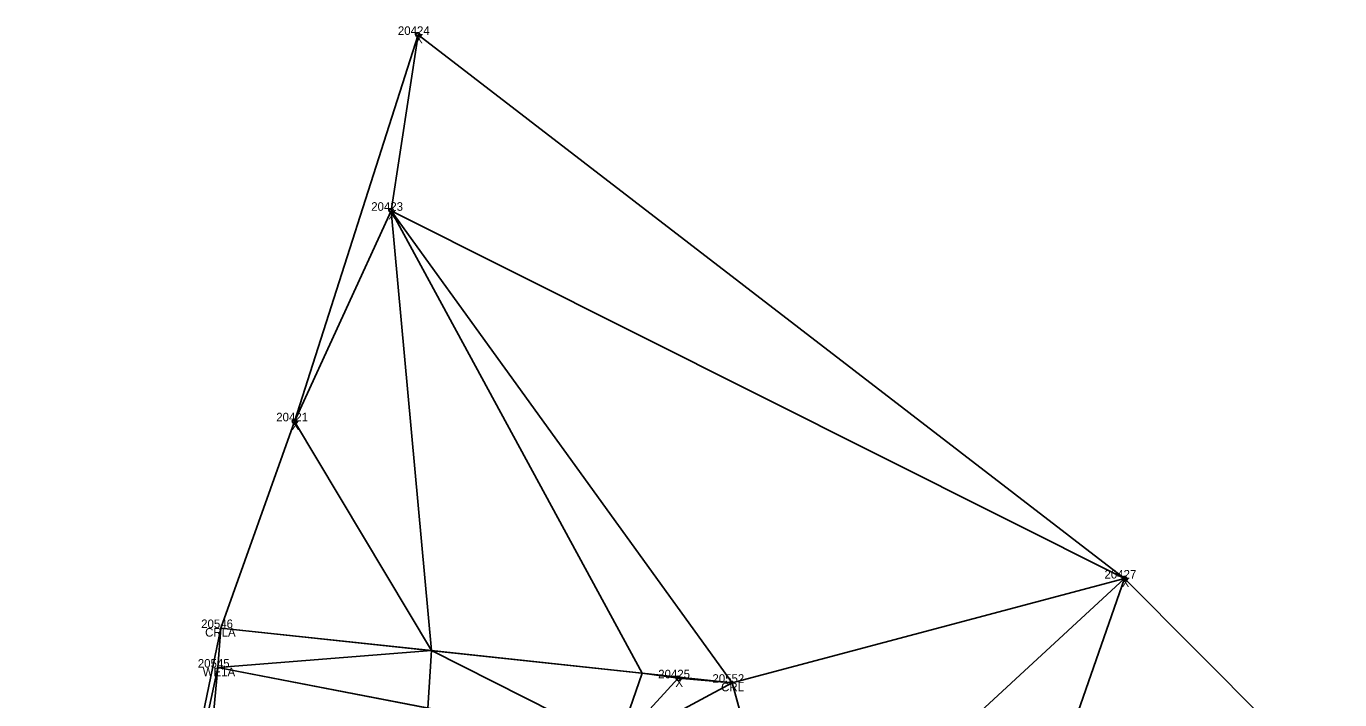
# Model space of a CAD drawing. Extents: x 1966740 to 1969291, y 1117379 to 1118460.
# Drawn here: x 1967829.6 to 1967983.3, y 1118381.7 to 1118460.4 of the extents above; entities that cross this region are included whole.
import ezdxf

# ---------------------------------------------------------------- set-up
doc = ezdxf.new("R2010")
doc.units = 0
for name, color, linetype in [('Level 10', 7, 'Continuous'), ('Level 30', 7, 'Continuous'), ('Level 35', 7, 'Continuous'), ('Level 50', 7, 'Continuous'), ('Level 52', 7, 'Continuous'), ('Level 60', 7, 'Continuous'), ('Level 61', 7, 'Continuous'), ('Level 62', 7, 'Continuous')]:
    doc.layers.add(name, color=color, linetype=linetype)

msp = doc.modelspace()

# ---------------------------------------------------------------- linework, layer by layer
at = {"layer": 'Level 10'}
for points in [[(1967852.4, 1118390.04), (1967912.21, 1118383.64), (1967925.08, 1118336.82), (1967944.14, 1118294.4), (1967946.67, 1118243.15), (1967961.58, 1118191.28), (1967922.84, 1118148.62), (1967880.18, 1118117.11), (1967858.72, 1118073.64), (1967843.96, 1118030.69), (1967829.77, 1117984.65), (1967829.63, 1117934.73), (1967834.65, 1117903.36)], [(1967852.05, 1118385.41), (1967898.77, 1118376.41), (1967924.08, 1118337.23), (1967939.81, 1118294.93), (1967943.5, 1118242.16), (1967952.29, 1118191.75), (1967920.83, 1118149.81), (1967879.07, 1118118.61), (1967857.7, 1118074.04)]]:
    msp.add_lwpolyline(points, dxfattribs=at)
at = {"layer": 'Level 30'}
for centre in [(1967875.46, 1118459.42), (1967872.32, 1118438.85), (1967860.99, 1118414.22), (1967958.1, 1118395.83), (1967905.89, 1118384.16)]:
    msp.add_circle(centre, 0.25, dxfattribs=at)
at = {"layer": 'Level 35'}
for points in [[(1967860.99, 1118414.22), (1967875.46, 1118459.42), (1967872.32, 1118438.85)], [(1967872.32, 1118438.85), (1967875.46, 1118459.42), (1967958.1, 1118395.83)], [(1967860.99, 1118414.22), (1967872.32, 1118438.85), (1967877.03, 1118387.41)], [(1967872.32, 1118438.85), (1967958.1, 1118395.83), (1967912.21, 1118383.64)], [(1967872.32, 1118438.85), (1967912.21, 1118383.64), (1967901.66, 1118384.77)], [(1967872.32, 1118438.85), (1967901.66, 1118384.77), (1967877.03, 1118387.41)], [(1967852.4, 1118390.04), (1967860.99, 1118414.22), (1967877.03, 1118387.41)], [(1967912.21, 1118383.64), (1967958.1, 1118395.83), (1967918.83, 1118359.56)], [(1967918.83, 1118359.56), (1967958.1, 1118395.83), (1967939.99, 1118343.92)], [(1967939.99, 1118343.92), (1967958.1, 1118395.83), (1967983.26, 1118370.54)], [(1967836.22, 1118311.82), (1967852.4, 1118390.04), (1967852.05, 1118385.41)], [(1967852.05, 1118385.41), (1967852.4, 1118390.04), (1967877.03, 1118387.41)], [(1967852.05, 1118385.41), (1967877.03, 1118387.41), (1967876.59, 1118380.68)], [(1967876.59, 1118380.68), (1967877.03, 1118387.41), (1967898.77, 1118376.41)], [(1967877.03, 1118387.41), (1967901.66, 1118384.77), (1967898.77, 1118376.41)], [(1967836.22, 1118311.82), (1967852.05, 1118385.41), (1967848.72, 1118350.07)], [(1967848.72, 1118350.07), (1967852.05, 1118385.41), (1967876.59, 1118380.68)], [(1967898.77, 1118376.41), (1967901.66, 1118384.77), (1967905.89, 1118384.16)], [(1967901.66, 1118384.77), (1967912.21, 1118383.64), (1967905.89, 1118384.16)], [(1967898.77, 1118376.41), (1967905.89, 1118384.16), (1967912.21, 1118383.64)], [(1967898.77, 1118376.41), (1967912.21, 1118383.64), (1967918.83, 1118359.56)]]:
    msp.add_lwpolyline(points, close=True, dxfattribs=at)
at = {"layer": 'Level 50'}
for centre in [(1967852.4, 1118390.04), (1967852.05, 1118385.41), (1967912.21, 1118383.64)]:
    msp.add_circle(centre, 0.001, dxfattribs=at)

# ---------------------------------------------------------------- texts
at = {"layer": 'Level 52'}
for s, p in [('20424', (1967873.1, 1118459.42)), ('20423', (1967869.98, 1118438.85)), ('20421', (1967858.87, 1118414.22)), ('20427', (1967955.75, 1118395.83)), ('20425', (1967903.55, 1118384.16))]:
    msp.add_text(s, height=1, dxfattribs=at).set_placement(p)
at = {"layer": 'Level 60'}
for s, p in [('CRLA', (1967850.55, 1118389.04)), ('WE1A', (1967850.27, 1118384.41)), ('CRL', (1967910.91, 1118382.64))]:
    msp.add_text(s, height=1, dxfattribs=at).set_placement(p)
at = {"layer": 'Level 61'}
for s, p in [('20546', (1967850.09, 1118390.04)), ('20545', (1967849.7, 1118385.41)), ('20552', (1967909.89, 1118383.64))]:
    msp.add_text(s, height=1, dxfattribs=at).set_placement(p)
at = {"layer": 'Level 62'}
for p in [(1967875.13, 1118458.42), (1967871.99, 1118437.85), (1967860.66, 1118413.22), (1967957.76, 1118394.83), (1967905.56, 1118383.16)]:
    msp.add_text('X', height=1, dxfattribs=at).set_placement(p)

doc.saveas('drawing.dxf')
